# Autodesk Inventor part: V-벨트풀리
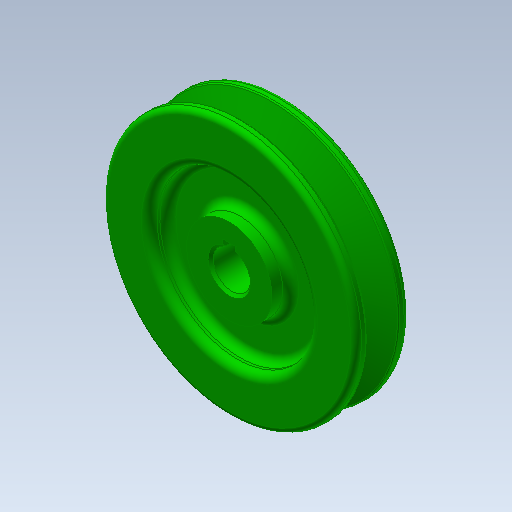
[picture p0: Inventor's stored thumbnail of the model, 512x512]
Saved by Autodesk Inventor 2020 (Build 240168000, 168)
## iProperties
Created: 2024-02
Part Number: V-벨트풀리
Material: 주철, 주조
Document SubType Name: Modeling
Designer: mdu-01
Density: 1 g/cm^3
Appearance: 기본값(1)
Author: mdu-01
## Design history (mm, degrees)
sketch "스케치1"
  geometry: L1 (0, 10)-(0, -10); L2 (0, 0)-(35, 0); L3 (0, 10)-(16, 10); L4 (16, 10)-(16, 6); L5 (19, 3)-(27, 3); L6 (30, 6)-(30, 7); L7 (33, 10)-(45.5, 10); L8 (47.5, 8)-(47.5, 6.346); L9 (47.146, 5.868)-(35.708, 2.37); L10 (0, -10)-(16, -10); L11 (16, -10)-(16, -6); L12 (19, -3)-(27, -3); L13 (30, -6)-(30, -7); L14 (33, -10)-(45.5, -10); L15 (47.5, -8)-(47.5, -6.346); L16 (47.146, -5.868)-(35.708, -2.37); L17 (35, 1.414)-(35, -1.414); L18 (7, 9)-(7, -9); L19 (9.3, 10)-(9.3, -10); L20 (-7, 10)-(-7, -10); L21 (7, 9)-(8, 10); L22 (7, -9)-(8, -10); A1 r 0.5 centre (47, 6.346) between (47.146, 5.868) and (47.5, 6.346); A2 r 0.5 centre (47, -6.346) between (47.5, -6.346) and (47.146, -5.868); A3 r 1 centre (36, 1.414) between (35.708, 2.37) and (35, 1.414); A4 r 1 centre (36, -1.414) between (35, -1.414) and (35.708, -2.37); A5 r 2 centre (45.5, 8) between (47.5, 8) and (45.5, 10); A6 r 2 centre (45.5, -8) between (45.5, -10) and (47.5, -8); A7 r 3 centre (33, 7) between (33, 10) and (30, 7); A8 r 3 centre (27, 6) between (27, 3) and (30, 6); A9 r 3 centre (27, -6) between (30, -6) and (27, -3); A10 r 3 centre (33, -7) between (30, -7) and (33, -10); A11 r 3 centre (19, -6) between (19, -3) and (16, -6); A12 r 3 centre (19, 6) between (16, 6) and (19, 3); 18 further points
  constraints: 44 end point, 35 point on line, 24 point on circle, 24 tangent, 12 centre point, 10 symmetric about line, 8 equal radius, 6 parallel, 4 midpoint, 3 perpendicular, 2 collinear, 1 coincident, 1 vertical
  dimensions: "d0" = 20 distance of L1.start L1.end; "d2" = 86 diameter of point (43, 4.6) L1; "d3" = 9.2 diameter of point (43, 4.6) L2; "d4" = 34 deg angle of L16 L9; "d5" = 4.5 distance from line of L8 point (43, 4.6); "d6" = 8 distance from line of L17 point (43, 4.6); "d7" = 14 diameter of L18 L1; "d8" = 16.3 distance between parallel lines of L19 L20; "d9" = 32 diameter of L11 L1; "d10" = 60 diameter of L13 L1; "d11" = 6 distance between parallel lines of L12 L5; "d12" = 0.5 radius of A1; "d13" = 1 radius of A3; "d14" = 2 radius of A5; "d15" = 1 distance of L18.start point (7, 10); "d17" = 1 distance of L18.end point (7, -10) (= d15); "d19" = 45 deg angle of L22 L18; "d20" = 45 deg angle of L21 L18; "d21" = 3 radius of A7
revolve "회전1" stored, may be unused: angle "d22" = 90 deg
extrude "돌출1" cut sketch "스케치1" stored distance "d23" = 5; taper "d24" = 0 deg
node "솔리드1"
